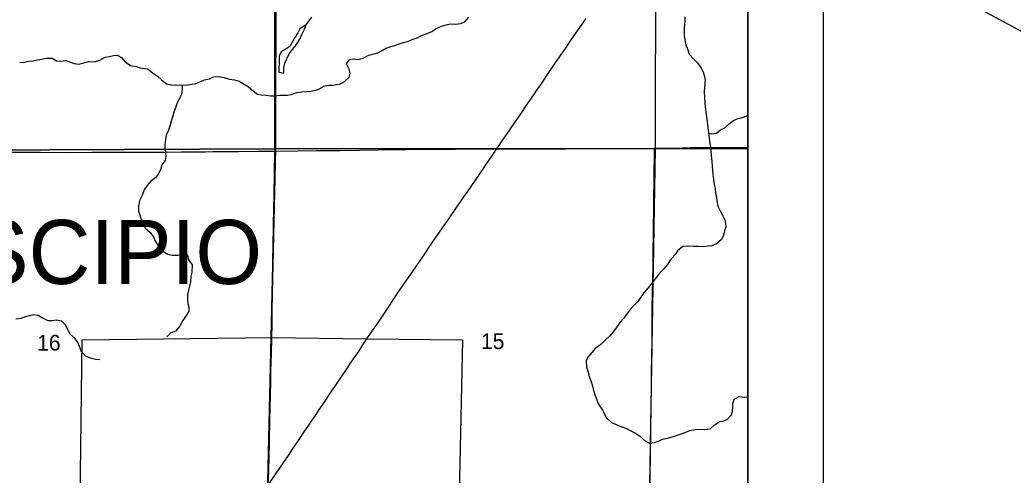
# Model space of a CAD drawing. Extents: x 0 to 34, y 0 to 22.
# Drawn here: x 7.933 to 9.252, y 16.311 to 16.916 of the extents above; entities that cross this region are included whole.
import ezdxf

# ---------------------------------------------------------------- set-up
doc = ezdxf.new("R2010")
doc.units = 0
for name, color, linetype in [('GM_X_Corporation', 7, 'Continuous'), ('GM_X_Minor_Lake', 7, 'Continuous'), ('GM_X_Minor_River', 7, 'Continuous'), ('GM_X_Section_Text', 7, 'Continuous'), ('GM_X_State_Route', 7, 'Continuous'), ('GM_X_Township_Road', 7, 'Continuous'), ('GM_X_Township_Text', 7, 'Continuous'), ('SH_Data', 7, 'Continuous'), ('SH_Text', 7, 'Continuous')]:
    doc.layers.add(name, color=color, linetype=linetype)

msp = doc.modelspace()

# ---------------------------------------------------------------- linework, layer by layer
at = {"layer": 'GM_X_Corporation'}
for points in [[(2.1, 20.7197), (2.1, 14.1), (8.9, 14.1), (8.9, 20.772)], [(8.9, 14.7391), (8.9, 17.776)]]:
    msp.add_lwpolyline(points, dxfattribs=at)
for points in [[(8.273, 17.2326), (8.4958, 17.232), (8.497, 17.2458), (8.7774, 17.2456), (8.7767, 16.7446), (8.2722, 16.7445)], [(8.9, 16.7447), (8.9, 17.2448), (8.7774, 17.2456), (8.7767, 16.7446)], [(7.7682, 17.2274), (8.273, 17.2326), (8.2722, 16.7445), (7.7697, 16.7421)], [(7.7697, 16.7421), (8.2722, 16.7445), (8.261, 16.2438), (7.7617, 16.2408)], [(8.2722, 16.7445), (8.7767, 16.7446), (8.7683, 16.245), (8.261, 16.2438)], [(8.9, 16.2445), (8.9, 16.7447), (8.7767, 16.7446), (8.7683, 16.245)], [(8.0124, 16.2409), (8.0155, 16.4902), (8.2673, 16.4933), (8.3935, 16.4919), (8.5207, 16.4903), (8.5153, 16.2434), (8.4387, 16.2432), (8.4363, 16.062), (8.3655, 16.0616), (8.3649, 15.9933), (8.2628, 15.9935), (8.0541, 15.99), (8.0137, 15.9892)]]:
    msp.add_lwpolyline(points, close=True, dxfattribs=at)
at = {"layer": 'GM_X_Minor_Lake'}
for points in [[(8.3129, 16.909), (8.3045, 16.9039), (8.3022, 16.8984), (8.2982, 16.8922), (8.2955, 16.8873), (8.2913, 16.8805), (8.2866, 16.8771), (8.2801, 16.8739), (8.2773, 16.8684), (8.2771, 16.8631), (8.277, 16.8576), (8.2768, 16.8523), (8.2768, 16.8462), (8.2798, 16.8457)], [(8.2798, 16.8457), (8.2832, 16.8451), (8.2836, 16.8519), (8.2848, 16.8581), (8.2873, 16.864), (8.2905, 16.8704), (8.2947, 16.8765), (8.3001, 16.8831), (8.3046, 16.8899), (8.3073, 16.8961), (8.3106, 16.9026), (8.3129, 16.909)]]:
    msp.add_lwpolyline(points, dxfattribs=at)
at = {"layer": 'GM_X_Minor_River'}
for points in [[(8.0459, 16.8663), (8.052, 16.8672), (8.0571, 16.8682), (8.0624, 16.8687), (8.0684, 16.8654), (8.0727, 16.8599), (8.0799, 16.8553), (8.0876, 16.8536), (8.0927, 16.8518), (8.0977, 16.8509), (8.1026, 16.8505), (8.1088, 16.8455), (8.1154, 16.8411), (8.121, 16.8359), (8.1276, 16.8308), (8.1342, 16.8292), (8.1401, 16.829), (8.1452, 16.8292), (8.1524, 16.8289), (8.1615, 16.8304), (8.1666, 16.8313), (8.173, 16.8339), (8.1778, 16.836), (8.1846, 16.8375), (8.1901, 16.8399), (8.1963, 16.8403), (8.2041, 16.8393), (8.2111, 16.8371), (8.2177, 16.8362), (8.2239, 16.8344), (8.2307, 16.8302), (8.2358, 16.8271), (8.2433, 16.8208), (8.2482, 16.8172), (8.2531, 16.8162), (8.2598, 16.8158), (8.2658, 16.8148), (8.2713, 16.815), (8.2779, 16.8155), (8.2832, 16.8157), (8.2881, 16.8157), (8.293, 16.8166), (8.3008, 16.8194), (8.3074, 16.8203), (8.3141, 16.8204), (8.3196, 16.821), (8.3256, 16.8223), (8.3307, 16.8241), (8.3362, 16.8275), (8.3427, 16.829), (8.3487, 16.8288), (8.3573, 16.8301), (8.3637, 16.8334), (8.37, 16.8397), (8.3717, 16.8451), (8.3704, 16.8501), (8.3665, 16.8573), (8.3705, 16.863), (8.3756, 16.8641), (8.3828, 16.8633), (8.3889, 16.8648), (8.3964, 16.8689), (8.4036, 16.8704), (8.4084, 16.8721), (8.4139, 16.8749), (8.4194, 16.8781), (8.4256, 16.8803), (8.4309, 16.8818), (8.4366, 16.8838), (8.4435, 16.8863), (8.4488, 16.8876), (8.4539, 16.8898), (8.4605, 16.8919), (8.4656, 16.8945), (8.4725, 16.8973), (8.4799, 16.9003), (8.4848, 16.9037), (8.4928, 16.9074), (8.499, 16.9093), (8.5045, 16.9104), (8.5119, 16.9102), (8.5181, 16.9111), (8.5238, 16.9133), (8.529, 16.9194)], [(8.3129, 16.909), (8.3207, 16.9192)], [(8.816, 16.9197), (8.8162, 16.9134), (8.8154, 16.9052), (8.8153, 16.8942), (8.8159, 16.8891), (8.8175, 16.8827), (8.82, 16.8758), (8.8219, 16.8703), (8.8275, 16.864), (8.8328, 16.8585), (8.8377, 16.8517), (8.8403, 16.8469), (8.8418, 16.842), (8.8431, 16.8361), (8.8427, 16.8311), (8.8421, 16.826), (8.8417, 16.8201), (8.8423, 16.8122), (8.8428, 16.8055), (8.843, 16.8004), (8.8441, 16.793), (8.845, 16.7868), (8.8457, 16.7809), (8.8461, 16.7757), (8.8472, 16.7691), (8.8478, 16.763), (8.8483, 16.7581), (8.8494, 16.7516), (8.8502, 16.7465), (8.8505, 16.7414), (8.8509, 16.7355), (8.8518, 16.7277), (8.8523, 16.7213), (8.8529, 16.7156), (8.8532, 16.7107), (8.8542, 16.7034), (8.8553, 16.697), (8.8562, 16.6915), (8.8569, 16.6854), (8.858, 16.6807), (8.8586, 16.6752), (8.8601, 16.6683), (8.8631, 16.6617), (8.8661, 16.6563), (8.8693, 16.6499), (8.87, 16.6448), (8.8704, 16.64), (8.8689, 16.6351), (8.8673, 16.6296), (8.8648, 16.6239), (8.8584, 16.6181), (8.8521, 16.6153), (8.8472, 16.6149), (8.8404, 16.614), (8.8337, 16.6146), (8.8275, 16.6146), (8.8201, 16.615), (8.8133, 16.6145), (8.8063, 16.6086), (8.8032, 16.6037), (8.7966, 16.5964), (8.7933, 16.5905), (8.7882, 16.585), (8.7823, 16.5792), (8.7783, 16.5737), (8.7745, 16.5682), (8.7672, 16.5597), (8.7615, 16.5527), (8.7575, 16.547), (8.7539, 16.5419), (8.748, 16.5357), (8.7435, 16.5308), (8.7395, 16.5253), (8.7351, 16.5191), (8.7298, 16.5134), (8.7261, 16.5081), (8.7214, 16.5017), (8.7159, 16.4953), (8.7107, 16.4903), (8.7039, 16.4839), (8.6974, 16.4792), (8.6927, 16.4734), (8.6877, 16.4677), (8.6851, 16.4628), (8.6856, 16.454), (8.6875, 16.4476), (8.6888, 16.4428), (8.6908, 16.4371), (8.6929, 16.4305), (8.6944, 16.425), (8.6966, 16.4176), (8.6987, 16.4117), (8.7004, 16.4067), (8.703, 16.402), (8.7068, 16.3969)], [(7.9326, 16.859), (7.939, 16.8595), (7.9445, 16.8608), (7.9504, 16.8612), (7.9562, 16.8628), (7.9613, 16.8634), (7.968, 16.8647), (7.9755, 16.8648), (7.9816, 16.8614), (7.9871, 16.8608), (7.9935, 16.8617), (7.9986, 16.8598), (8.0048, 16.8578), (8.0112, 16.8568), (8.0179, 16.8585), (8.0245, 16.8604), (8.0317, 16.8598), (8.0389, 16.862), (8.0459, 16.8663)], [(8.1485, 16.8291), (8.1482, 16.8238), (8.1476, 16.8164), (8.1447, 16.8113), (8.1418, 16.8053), (8.1395, 16.7989), (8.1372, 16.7932), (8.1353, 16.7864), (8.1338, 16.7809), (8.132, 16.7746), (8.1301, 16.7691), (8.1272, 16.7623), (8.1264, 16.7566), (8.1254, 16.7498), (8.1254, 16.7451), (8.126, 16.7403), (8.1265, 16.7343), (8.1259, 16.729), (8.1215, 16.7229), (8.1194, 16.7165), (8.1165, 16.7106), (8.1131, 16.7057), (8.1062, 16.7008), (8.1017, 16.6957), (8.098, 16.6899), (8.0953, 16.6823), (8.0917, 16.6753), (8.0903, 16.6681), (8.0903, 16.6615), (8.0922, 16.6563), (8.094, 16.6504), (8.097, 16.6455), (8.0991, 16.639), (8.1053, 16.6337), (8.1102, 16.6272), (8.1122, 16.6225), (8.115, 16.6175), (8.1186, 16.612), (8.124, 16.6072), (8.1293, 16.6045), (8.1352, 16.603), (8.142, 16.603), (8.1498, 16.6044), (8.1554, 16.6033), (8.1567, 16.5968), (8.1616, 16.5903), (8.1613, 16.5805), (8.16, 16.5752), (8.1594, 16.5678), (8.1582, 16.5619), (8.1568, 16.5564), (8.1553, 16.5502), (8.1555, 16.5441), (8.156, 16.5388), (8.1573, 16.5337), (8.1571, 16.5285), (8.154, 16.5231), (8.149, 16.5155), (8.1452, 16.5085), (8.1393, 16.5021), (8.1327, 16.4993), (8.1279, 16.4946)], [(8.8476, 16.7646), (8.8521, 16.7641), (8.858, 16.7653), (8.8633, 16.7696), (8.8694, 16.7722), (8.8753, 16.7781), (8.8808, 16.7822), (8.8857, 16.7843), (8.8922, 16.786), (8.8986, 16.7882), (8.9, 16.7883)], [(7.9274, 16.5183), (7.9344, 16.5194), (7.9391, 16.5209), (7.9454, 16.5227), (7.9514, 16.5242), (7.9571, 16.523), (7.9635, 16.5192), (7.9701, 16.5161), (7.9754, 16.5159), (7.9809, 16.5168), (7.9877, 16.5158), (7.9926, 16.5111), (7.9963, 16.5035), (7.9989, 16.4985), (8.0044, 16.4937), (8.0091, 16.4875), (8.0113, 16.4818), (8.0143, 16.4749), (8.0201, 16.4692), (8.0262, 16.4663), (8.0332, 16.4646), (8.039, 16.4644)], [(8.7068, 16.3969), (8.7096, 16.3915), (8.712, 16.3866), (8.7186, 16.3807), (8.7281, 16.3766), (8.7338, 16.3745), (8.7387, 16.3724), (8.7445, 16.3694), (8.7506, 16.3663), (8.7572, 16.3617), (8.7619, 16.3568), (8.7691, 16.3529), (8.7759, 16.3539), (8.7809, 16.3557), (8.7864, 16.3584), (8.7915, 16.3593), (8.7962, 16.3604), (8.8023, 16.3625), (8.8087, 16.3647), (8.8152, 16.3668), (8.8228, 16.3698), (8.83, 16.3712), (8.8364, 16.3718), (8.8425, 16.3714), (8.8498, 16.3721), (8.8555, 16.3776), (8.8624, 16.3817), (8.8675, 16.3828), (8.8722, 16.3843), (8.8781, 16.3906), (8.8795, 16.3957), (8.8797, 16.4006), (8.8801, 16.4057), (8.8816, 16.4114), (8.8883, 16.4152), (8.8953, 16.4142), (8.9, 16.4148)]]:
    msp.add_lwpolyline(points, dxfattribs=at)
at = {"layer": 'GM_X_State_Route'}
for points in [[(8.2674, 16.4931), (8.2677, 16.512), (8.268, 16.5306), (8.2683, 16.5499), (8.2687, 16.5806), (8.269, 16.5971), (8.2692, 16.6142), (8.2697, 16.6434), (8.27, 16.6645), (8.2704, 16.6832), (8.2709, 16.7111), (8.2713, 16.7414), (8.2713, 16.7481), (8.2714, 16.7972), (8.2714, 16.8199), (8.2715, 16.8429), (8.2715, 16.8612), (8.2715, 16.8904), (8.2716, 16.9094), (8.2716, 16.938)], [(8.3937, 16.4916), (8.3977, 16.4977), (8.402, 16.504), (8.4073, 16.5114), (8.4249, 16.5379), (8.4288, 16.5438), (8.434, 16.5515), (8.438, 16.5574), (8.4451, 16.5677), (8.4551, 16.5823), (8.4679, 16.6006), (8.4802, 16.6188), (8.4881, 16.6305), (8.5019, 16.65), (8.5111, 16.6637), (8.5181, 16.674), (8.5226, 16.6804), (8.5264, 16.686), (8.5313, 16.6931), (8.5388, 16.7041), (8.5485, 16.7182), (8.5528, 16.7246), (8.5578, 16.7318), (8.5632, 16.7397), (8.5663, 16.7443), (8.5727, 16.7536), (8.5797, 16.7638), (8.5913, 16.7808), (8.5946, 16.7856), (8.5972, 16.7895), (8.6004, 16.7941), (8.6059, 16.8024), (8.6101, 16.8086), (8.6163, 16.8175), (8.6194, 16.8221), (8.6242, 16.829), (8.6383, 16.8499), (8.6501, 16.867), (8.6557, 16.8752), (8.6661, 16.8904), (8.6849, 16.9174)], [(8.2627, 16.2971), (8.263, 16.3067), (8.2633, 16.3163), (8.2637, 16.3356), (8.2642, 16.3539), (8.2648, 16.3862), (8.2651, 16.4002), (8.2656, 16.4151), (8.2661, 16.4362), (8.2663, 16.4483), (8.2667, 16.4611), (8.267, 16.4716), (8.2674, 16.4931)], [(8.2815, 16.325), (8.2894, 16.3367), (8.2951, 16.3452), (8.2979, 16.3493), (8.3045, 16.3591), (8.3106, 16.3681), (8.3167, 16.3771), (8.3209, 16.3835), (8.3253, 16.39), (8.3309, 16.3983), (8.3381, 16.4088), (8.342, 16.4147), (8.3472, 16.4225), (8.3515, 16.429), (8.3678, 16.4532), (8.3729, 16.4607), (8.3803, 16.4714), (8.3843, 16.4773), (8.3876, 16.4823), (8.3937, 16.4916)], [(8.2627, 16.2971), (8.268, 16.305), (8.2767, 16.3179), (8.2815, 16.325)]]:
    msp.add_lwpolyline(points, dxfattribs=at)
at = {"layer": 'GM_X_Township_Road'}
for points in [[(8.5663, 16.7443), (8.5782, 16.7443), (8.5919, 16.7443), (8.6087, 16.7444), (8.6202, 16.7444), (8.6575, 16.7445), (8.7063, 16.7447), (8.7352, 16.7448), (8.7665, 16.7449), (8.7759, 16.7451)], [(8.7694, 16.2437), (8.7694, 16.2467), (8.7694, 16.2578), (8.7697, 16.2749), (8.7699, 16.2992), (8.77, 16.3138), (8.7704, 16.3327), (8.7709, 16.375), (8.7712, 16.3983), (8.7718, 16.4315), (8.7719, 16.4498), (8.7722, 16.466), (8.7725, 16.4918), (8.7727, 16.5141), (8.7729, 16.5321), (8.7733, 16.5523), (8.7736, 16.5697), (8.7739, 16.5884), (8.7742, 16.6089), (8.7743, 16.6306), (8.7749, 16.6738), (8.7752, 16.7067), (8.7758, 16.74), (8.7759, 16.7451)], [(8.7759, 16.7451), (8.793, 16.7454), (8.8122, 16.7458), (8.8237, 16.746), (8.8402, 16.746), (8.8591, 16.746), (8.8973, 16.7461), (8.9, 16.7461)], [(7.7706, 16.74), (7.7741, 16.74), (7.8005, 16.7401), (7.8458, 16.7401), (7.8691, 16.74), (7.9095, 16.7397), (7.9304, 16.7397), (7.9596, 16.7397), (7.9941, 16.7396), (8.0286, 16.7397), (8.0534, 16.7397), (8.0634, 16.7398), (8.0767, 16.7397), (8.0991, 16.7399), (8.1267, 16.7401), (8.1475, 16.7402), (8.169, 16.7404), (8.1795, 16.7405), (8.1892, 16.7406), (8.2041, 16.7408), (8.223, 16.7409), (8.2497, 16.7413), (8.2594, 16.7413), (8.2713, 16.7414)], [(8.2713, 16.7414), (8.3019, 16.7417), (8.3265, 16.742), (8.3408, 16.7421), (8.3579, 16.7423), (8.384, 16.7426), (8.4085, 16.7429), (8.4455, 16.7435), (8.4775, 16.7438), (8.4918, 16.7439), (8.5108, 16.744), (8.5434, 16.7443), (8.5614, 16.7443), (8.5663, 16.7443)]]:
    msp.add_lwpolyline(points, dxfattribs=at)
at = {"layer": 'SH_Data'}
for p, q in [((9, 21), (9, 14)), ((8.9, 20.9), (8.9, 14.1))]:
    msp.add_line(p, q, dxfattribs=at)
at = {"layer": 'SH_Text'}
msp.add_lwpolyline([(9.297, 16.882), (2.5966, 20.4971), (9.297, 17.6363)], close=True, dxfattribs=at)

# ---------------------------------------------------------------- texts
at = {"layer": 'GM_X_Section_Text'}
for s, p in [('16', (7.9557, 16.4761)), ('15', (8.5453, 16.4781))]:
    msp.add_text(s, height=0.02093, rotation=0, dxfattribs=at).set_placement(p)
at = {"layer": 'GM_X_Township_Text'}
msp.add_text('SCIPIO', height=0.08523, rotation=0, dxfattribs=at).set_placement((7.8682, 16.5646))

doc.saveas('drawing.dxf')
